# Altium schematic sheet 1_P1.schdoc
size 307 x 218 mm; Symbol: Drawing-Symbol_A4; Device: Drawing-Symbol_A4; @Project Name: AQI; @Page Count: 1; @Update Date: 2026-03-18; @Create Date: 2026-03-18; @Schematic Name: Schematic1; @Page No: 1; @Page Name: P1; Company: EasyEDA.com; Version: V1.0; Page Size: A4; @Create Time: 09:13:19; @Update Time: 14:13:26; Width: 1170; Height: 825; Region Start: 1; X Region Count: 6; Y Region Count: 4; Blade Width: 10; Title Block Position: 3; @Board Name: Board1
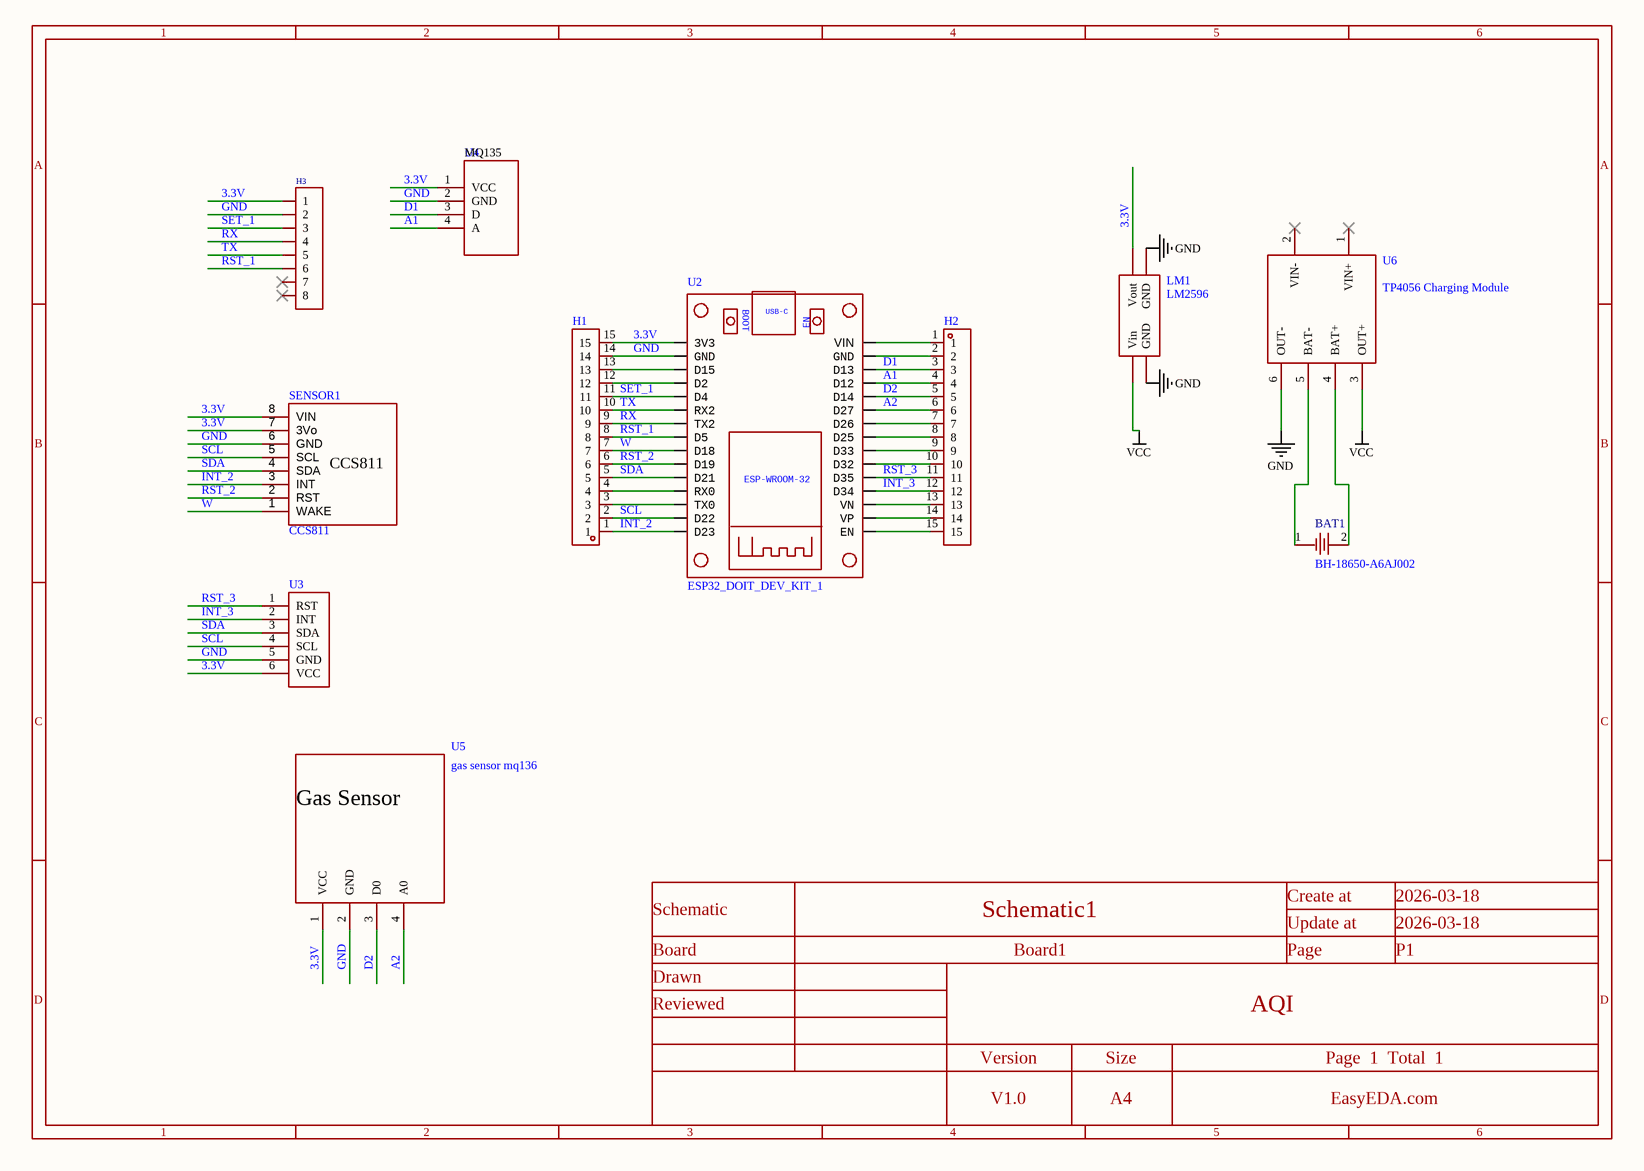
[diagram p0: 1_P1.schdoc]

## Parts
BAT1  BH-18650-A6AJ002  [BAT-TH_L77.0-W20.7_BH-18650-A6AJ002]
H1  (no value)  [HDR-TH_15P-P2.54-V-M]
H2  (no value)  [HDR-TH_15P-P2.54-V-M]
H3  (no value)  [HDR-TH_8P-P2.54-V-F-1]
LM1  LM2596  [LM2596-STEPDOWN-MODULE]
SENSOR1  CCS811  [CCS811-1]
U2  ESP32_DOIT_DEV_KIT_1  [ESP32 DOIT DEVKIT V1 mk2]
U3  (no value)  [sht31DFBoard]
U4  (no value)  [MQ135]
U5  gas sensor mq136  [GAS SENSOR]
U6  (no value)  [TP4056 Carging Module]

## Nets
GND: H1.14 H3.2 LM1.2(GND) LM1.4(GND) SENSOR1.6(GND) U2.4(GND) U3.5(GND) U4.2(GND) U5.2(GND) U6.6(OUT-)
VCC: LM1.1(Vin) U6.3(OUT+)
3.3V: H1.15 H3.1 LM1.3(Vout) SENSOR1.7(3Vo) SENSOR1.8(VIN) U2.1(3V3) U3.6(VCC) U4.1(VCC) U5.1(VCC)
A1: H2.4 U2.30(D12) U4.4(A)
A2: H2.6 U2.28(D27) U5.4(A0)
D1: H2.3 U2.31(D13) U4.3(D)
D2: H2.5 U2.29(D14) U5.3(D0)
INT_2: H1.1 SENSOR1.3(INT) U2.18(D23)
INT_3: H2.12 U2.22(D34) U3.2(INT)
RST_1: H1.8 H3.6 U2.11(D5)
RST_2: H1.6 SENSOR1.2(RST) U2.13(D19)
RST_3: H2.11 U2.23(D35) U3.1(RST)
RX: H1.9 H3.4 U2.10(TX2)
SCL: H1.2 SENSOR1.5(SCL) U2.17(D22) U3.4(SCL)
SDA: H1.5 SENSOR1.4(SDA) U2.14(D21) U3.3(SDA)
SET_1: H1.11 H3.3 U2.8(D4)
TX: H1.10 H3.5 U2.9(RX2)
W: H1.7 SENSOR1.1(WAKE) U2.12(D18)
NetBAT1_1: BAT1.1 U6.5(BAT-)
NetBAT1_2: BAT1.2 U6.4(BAT+)
NetH1_3: H1.3 U2.16(TX0)
NetH1_4: H1.4 U2.15(RX0)
NetH1_12: H1.12 U2.7(D2)
NetH1_13: H1.13 U2.6(D15)
NetH2_1: H2.1 U2.36(VIN)
NetH2_2: H2.2 U2.35(GND)
NetH2_7: H2.7 U2.27(D26)
NetH2_8: H2.8 U2.26(D25)
NetH2_9: H2.9 U2.25(D33)
NetH2_10: H2.10 U2.24(D32)
NetH2_13: H2.13 U2.21(VN)
NetH2_14: H2.14 U2.20(VP)
NetH2_15: H2.15 U2.19(EN)

Not connected (* = marked no-connect by the designer): H3 7* 8*; U6 1(VIN+)* 2(VIN-)*

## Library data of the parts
BAT1 = BH-18650-A6AJ002: Manufacturer: MYOUNG(美阳); Add into BOM: yes; Contact coating: Nickel plated
H1 H2 = HDR-M_2.54_1x15P: Symbol: HDR_2.54-1x15P; Convert to PCB: yes
H3 = HDR-F_2.54_1x8P: Manufacturer: BOOMELE(博穆精密); Manufacturer Part: 2.54-1*8P母环保; Symbol: Header-Female-2.54_1x8; Add into BOM: yes
LM1 = LM2596: Manufacturer: Aliexpress; Convert to PCB: yes
SENSOR1 = CCS811: Add into BOM: yes; 3DModel: CCS811_V4
U2 = ESP32: Manufacturer: Espressif; Manufacturer Part: ESP32_DOIT_DEVKIT_30 PIN; Add into BOM: yes; 3DModel: ESP32-DOIT
U3 = sht31DFBoard: Add into BOM: yes
U4 = MQ135: Add into BOM: yes
U5 = gas sensor mq136: Add into BOM: yes
U6 = TP4056 Charging Module: Add into BOM: yes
